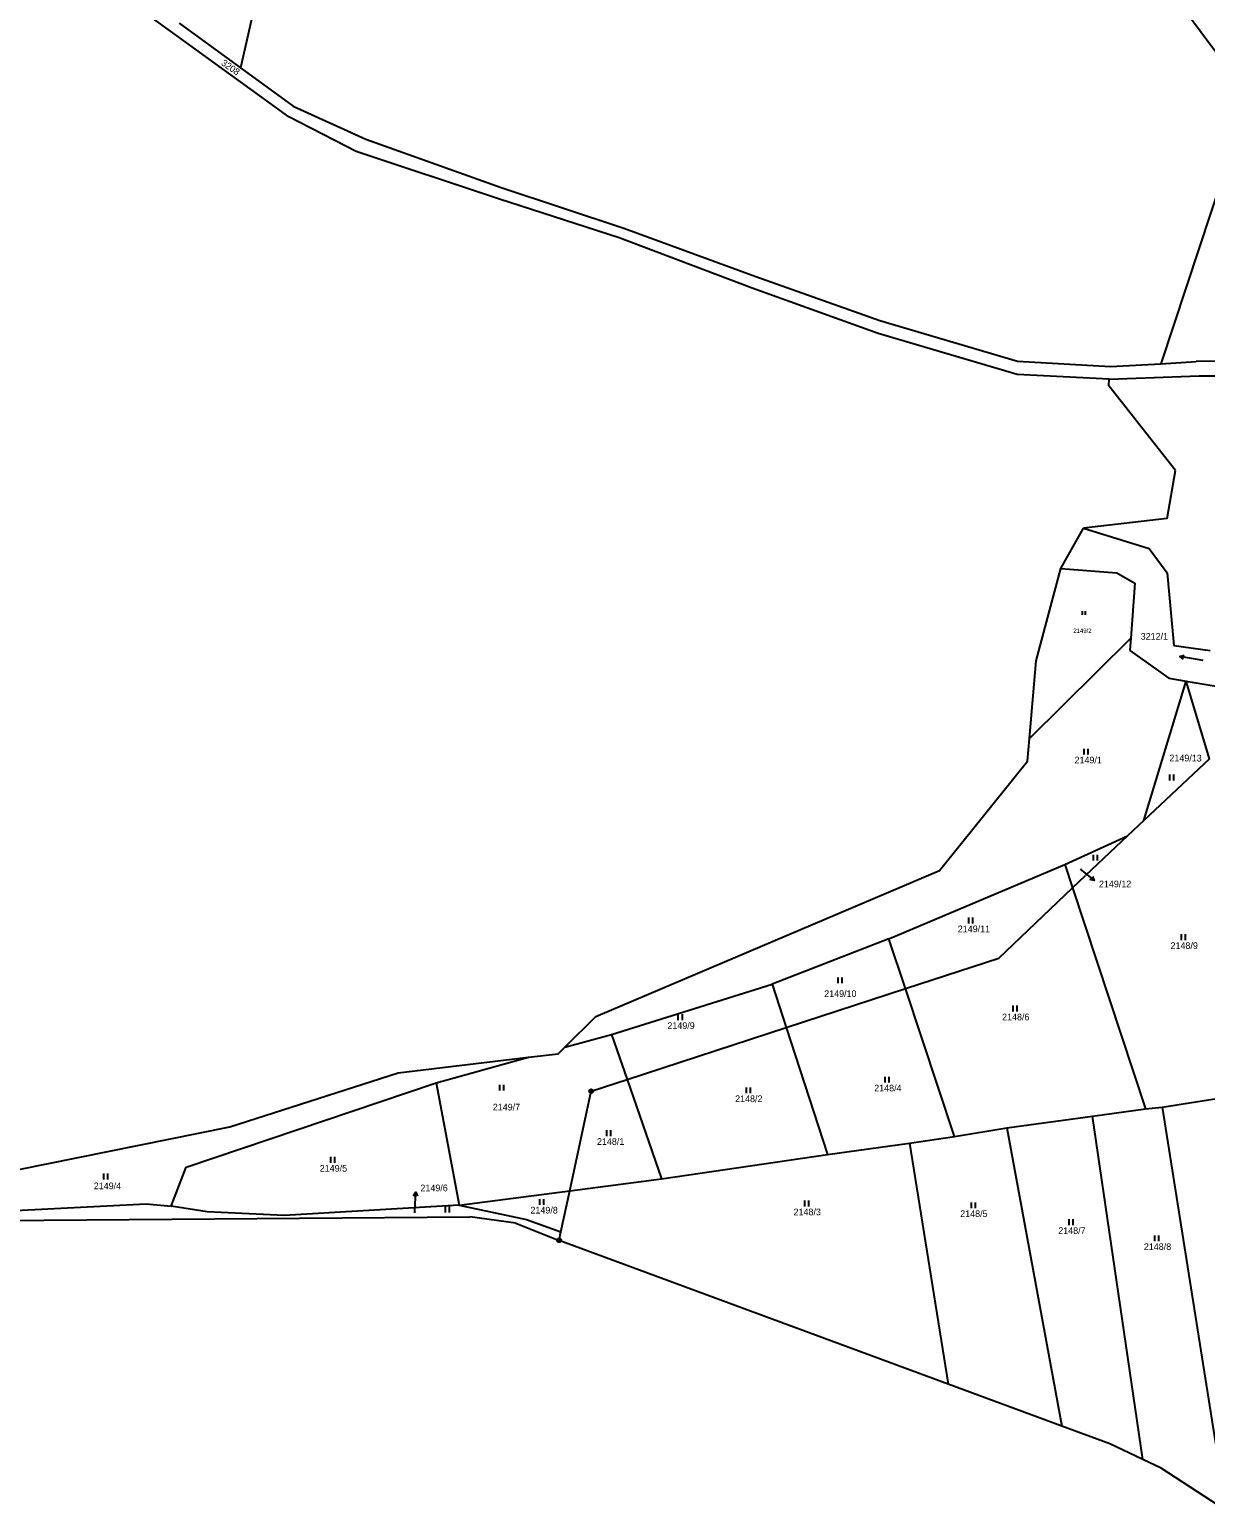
# Model space of a CAD drawing. Extents: x -736345 to -729997, y -1130177 to -1122501.
# Drawn here: x -732466.5 to -732167.4, y -1129158.7 to -1128781.9 of the extents above; entities that cross this region are included whole.
import ezdxf

# ---------------------------------------------------------------- set-up
doc = ezdxf.new("R2010")
doc.units = 0
for name, color, linetype in [('Vrstva 1', 7, 'Continuous'), ('Vrstva 13', 7, 'Continuous'), ('Vrstva 16', 7, 'Continuous'), ('Vrstva 18', 7, 'Continuous'), ('Vrstva 25', 7, 'Continuous')]:
    doc.layers.add(name, color=color, linetype=linetype)

msp = doc.modelspace()

# ---------------------------------------------------------------- linework, layer by layer
at = {"layer": 'Vrstva 1'}
for points in [[(-732403.79, -1128752.06), (-732412.82, -1128791.63)], [(-732184.86, -1128760.46), (-732156.26, -1128798.96)], [(-732429.09, -1128783.39), (-732455.66, -1128764.15)], [(-732428.4, -1128780.25), (-732412.82, -1128791.63)], [(-732400.49, -1128804.08), (-732429.09, -1128783.39)], [(-732412.82, -1128791.63), (-732399.38, -1128801.44)], [(-732156.26, -1128798.96), (-732178.67, -1128866.93)], [(-732383.4, -1128812.97), (-732400.49, -1128804.08)], [(-732399.38, -1128801.44), (-732380.93, -1128809.83)], [(-732380.93, -1128809.83), (-732346.49, -1128822.07)], [(-732347.2, -1128825.01), (-732383.4, -1128812.97)], [(-732346.49, -1128822.07), (-732315.31, -1128832.42)], [(-732316.45, -1128834.91), (-732347.2, -1128825.01)], [(-732282.67, -1128847.73), (-732316.45, -1128834.91)], [(-732315.31, -1128832.42), (-732281.69, -1128844.73)], [(-732281.69, -1128844.73), (-732250.2, -1128855.96)], [(-732250.59, -1128859.26), (-732282.67, -1128847.73)], [(-732250.2, -1128855.96), (-732215.16, -1128866.26)], [(-732215.21, -1128869.67), (-732250.59, -1128859.26)], [(-732215.16, -1128866.26), (-732191.49, -1128867.68)], [(-732191.49, -1128867.68), (-732178.67, -1128866.93)], [(-732178.67, -1128866.93), (-732169.67, -1128866.4)], [(-732133.66, -1128866.12), (-732169.67, -1128866.4)], [(-732191.84, -1128870.86), (-732215.21, -1128869.67)], [(-732191.95, -1128872.59), (-732191.84, -1128870.86)], [(-732174.99, -1128894.07), (-732191.95, -1128872.59)], [(-732191.84, -1128870.86), (-732168.96, -1128870.02)], [(-732168.96, -1128870.02), (-732133.37, -1128870.01)], [(-732177.12, -1128906.34), (-732174.99, -1128894.07)], [(-732177.12, -1128906.34), (-732198.39, -1128908.78)], [(-732204.13, -1128919.02), (-732198.39, -1128908.78)], [(-732198.39, -1128908.78), (-732181.69, -1128913.92)], [(-732181.69, -1128913.92), (-732177.09, -1128920.13)], [(-732210.4, -1128942.49), (-732204.13, -1128919.02)], [(-732204.13, -1128919.02), (-732189.88, -1128920.1)], [(-732189.88, -1128920.1), (-732185.33, -1128922.74)], [(-732177.09, -1128920.13), (-732175.38, -1128938.61)], [(-732185.33, -1128922.74), (-732186.34, -1128936.72)], [(-732212.14, -1128962.28), (-732186.34, -1128936.72)], [(-732186.34, -1128936.72), (-732186.57, -1128939.86)], [(-732186.57, -1128939.86), (-732176.67, -1128946.96)], [(-732175.38, -1128938.61), (-732166.12, -1128939.86)], [(-732212.14, -1128962.28), (-732210.4, -1128942.49)], [(-732182.99, -1128983.15), (-732172.28, -1128947.69)], [(-732176.67, -1128946.96), (-732172.28, -1128947.69)], [(-732172.28, -1128947.69), (-732149.35, -1128951.5)], [(-732166.29, -1128967.43), (-732172.28, -1128947.69)], [(-732212.64, -1128968.03), (-732212.14, -1128962.28)], [(-732234.98, -1128995.89), (-732212.64, -1128968.03)], [(-732166.29, -1128967.43), (-732182.99, -1128983.15)], [(-732182.99, -1128983.15), (-732187.16, -1128987.08)], [(-732203.12, -1128994.33), (-732187.16, -1128987.08)], [(-732187.16, -1128987.08), (-732197.89, -1128997.17)], [(-732322.43, -1129033.05), (-732234.98, -1128995.89)], [(-732247.85, -1129013.23), (-732203.12, -1128994.33)], [(-732203.12, -1128994.33), (-732201.15, -1129000.28)], [(-732201.15, -1129000.28), (-732197.89, -1128997.17)], [(-732219.92, -1129018.18), (-732201.15, -1129000.28)], [(-732201.15, -1129000.28), (-732182.56, -1129056.46)], [(-732247.85, -1129013.23), (-732277.58, -1129024.82)], [(-732243.64, -1129025.92), (-732247.85, -1129013.23)], [(-732243.64, -1129025.92), (-732219.92, -1129018.18)], [(-732318.45, -1129037.55), (-732277.58, -1129024.82)], [(-732277.58, -1129024.82), (-732274, -1129035.83)], [(-732274, -1129035.83), (-732243.64, -1129025.92)], [(-732231.16, -1129063.53), (-732243.64, -1129025.92)], [(-732330.32, -1129040.84), (-732322.43, -1129033.05)], [(-732330.32, -1129040.84), (-732318.45, -1129037.55)], [(-732318.45, -1129037.55), (-732314.48, -1129049.04)], [(-732314.48, -1129049.04), (-732274, -1129035.83)], [(-732274, -1129035.83), (-732263.47, -1129068.16)], [(-732339.56, -1129043.39), (-732332.01, -1129042.5)], [(-732332.01, -1129042.5), (-732330.32, -1129040.84)], [(-732372.67, -1129047.32), (-732339.56, -1129043.39)], [(-732363.08, -1129049.9), (-732339.56, -1129043.39)], [(-732426.61, -1129071.37), (-732363.08, -1129049.9)], [(-732415.55, -1129061.1), (-732372.67, -1129047.32)], [(-732363.08, -1129049.9), (-732357.21, -1129081.02)], [(-732323.6, -1129052.02), (-732314.48, -1129049.04)], [(-732314.48, -1129049.04), (-732305.73, -1129074.33)], [(-732329.06, -1129077.36), (-732323.6, -1129052.02)], [(-732178.32, -1129056.08), (-732161.2, -1129053.37)], [(-732196.08, -1129058.4), (-732182.56, -1129056.46)], [(-732182.56, -1129056.46), (-732178.32, -1129056.08)], [(-732178.32, -1129056.08), (-732162.1, -1129158.66)], [(-732477.27, -1129073.55), (-732415.55, -1129061.1)], [(-732231.16, -1129063.53), (-732217.9, -1129061.34)], [(-732217.9, -1129061.34), (-732196.08, -1129058.4)], [(-732217.9, -1129061.34), (-732203.92, -1129137.23)], [(-732183.25, -1129145.73), (-732196.08, -1129058.4)], [(-732242.62, -1129065.2), (-732231.16, -1129063.53)], [(-732305.73, -1129074.33), (-732263.47, -1129068.16)], [(-732263.47, -1129068.16), (-732242.62, -1129065.2)], [(-732242.62, -1129065.2), (-732232.81, -1129126.55)], [(-732430.47, -1129081.29), (-732426.61, -1129071.37)], [(-732329.06, -1129077.36), (-732305.73, -1129074.33)], [(-732357.21, -1129081.02), (-732329.06, -1129077.36)], [(-732331.31, -1129087.77), (-732329.06, -1129077.36)], [(-732485.24, -1129083.15), (-732436.78, -1129080.64)], [(-732436.78, -1129080.64), (-732430.47, -1129081.29)], [(-732421.26, -1129082.73), (-732430.47, -1129081.29)], [(-732401.7, -1129083.63), (-732421.26, -1129082.73)], [(-732357.21, -1129081.02), (-732401.7, -1129083.63)], [(-732357.21, -1129081.02), (-732340.08, -1129084.65)], [(-732340.08, -1129084.65), (-732331.31, -1129087.77)], [(-732331.78, -1129089.96), (-732331.31, -1129087.77)]]:
    msp.add_lwpolyline(points, dxfattribs=at)
at = {"layer": 'Vrstva 13'}
for points in [[(-732484.55, -1129084.96), (-732354.52, -1129083.95)], [(-732342.75, -1129085.62), (-732354.52, -1129083.95)], [(-732342.75, -1129085.62), (-732331.78, -1129089.96)], [(-732232.81, -1129126.55), (-732331.78, -1129089.96)], [(-732203.92, -1129137.23), (-732232.81, -1129126.55)], [(-732191.63, -1129141.77), (-732203.92, -1129137.23)], [(-732183.25, -1129145.73), (-732191.63, -1129141.77)], [(-732178.61, -1129147.93), (-732183.25, -1129145.73)], [(-732162.1, -1129158.66), (-732178.61, -1129147.93)]]:
    msp.add_lwpolyline(points, dxfattribs=at)
at = {"layer": 'Vrstva 16'}
for points in [[(-732199.2, -1128995.53), (-732197.96, -1128996.54)], [(-732368.48, -1129082.98), (-732368.38, -1129080.67)]]:
    msp.add_lwpolyline(points, dxfattribs=at)
at = {"layer": 'Vrstva 25'}
for points in [[(-732198.586, -1128930.852), (-732198.586, -1128929.847)], [(-732197.893, -1128930.852), (-732197.893, -1128929.847)], [(-732172.965, -1128942.073), (-732173.868, -1128941.415), (-732172.8, -1128941.087)], [(-732167.952, -1128942.405), (-732173.868, -1128941.415)], [(-732198.177, -1128966.385), (-732198.177, -1128964.885)], [(-732197.143, -1128966.385), (-732197.143, -1128964.885)], [(-732176.387, -1128972.945), (-732176.387, -1128971.445)], [(-732175.353, -1128972.945), (-732175.353, -1128971.445)], [(-732195.817, -1128993.355), (-732195.817, -1128991.855)], [(-732194.783, -1128993.355), (-732194.783, -1128991.855)], [(-732197.96, -1128996.54), (-732195.639, -1128998.44)], [(-732196.096, -1128997.419), (-732195.639, -1128998.44), (-732196.73, -1128998.193)], [(-732227.577, -1129009.335), (-732227.577, -1129007.835)], [(-732226.543, -1129009.335), (-732226.543, -1129007.835)], [(-732173.427, -1129013.595), (-732173.427, -1129012.095)], [(-732172.393, -1129013.595), (-732172.393, -1129012.095)], [(-732260.757, -1129024.555), (-732260.757, -1129023.055)], [(-732259.723, -1129024.555), (-732259.723, -1129023.055)], [(-732216.277, -1129031.745), (-732216.277, -1129030.245)], [(-732215.243, -1129031.745), (-732215.243, -1129030.245)], [(-732301.447, -1129033.955), (-732301.447, -1129032.455)], [(-732300.413, -1129033.955), (-732300.413, -1129032.455)], [(-732248.807, -1129049.825), (-732248.807, -1129048.325)], [(-732247.773, -1129049.825), (-732247.773, -1129048.325)], [(-732346.837, -1129051.875), (-732346.837, -1129050.375)], [(-732345.803, -1129051.875), (-732345.803, -1129050.375)], [(-732284.127, -1129052.555), (-732284.127, -1129051.055)], [(-732283.093, -1129052.555), (-732283.093, -1129051.055)], [(-732319.647, -1129063.435), (-732319.647, -1129061.935)], [(-732318.613, -1129063.435), (-732318.613, -1129061.935)], [(-732389.847, -1129070.245), (-732389.847, -1129068.745)], [(-732388.813, -1129070.245), (-732388.813, -1129068.745)], [(-732447.567, -1129074.455), (-732447.567, -1129072.955)], [(-732446.533, -1129074.455), (-732446.533, -1129072.955)], [(-732368.792, -1129078.651), (-732368.25, -1129077.673), (-732367.794, -1129078.694)], [(-732368.38, -1129080.67), (-732368.25, -1129077.673)], [(-732336.667, -1129080.945), (-732336.667, -1129079.445)], [(-732335.633, -1129080.945), (-732335.633, -1129079.445)], [(-732269.257, -1129081.345), (-732269.257, -1129079.845)], [(-732268.223, -1129081.345), (-732268.223, -1129079.845)], [(-732360.647, -1129082.835), (-732360.647, -1129081.335)], [(-732359.613, -1129082.835), (-732359.613, -1129081.335)], [(-732226.887, -1129081.795), (-732226.887, -1129080.295)], [(-732225.853, -1129081.795), (-732225.853, -1129080.295)], [(-732202.027, -1129086.105), (-732202.027, -1129084.605)], [(-732200.993, -1129086.105), (-732200.993, -1129084.605)], [(-732180.197, -1129090.185), (-732180.197, -1129088.685)], [(-732179.163, -1129090.185), (-732179.163, -1129088.685)]]:
    msp.add_lwpolyline(points, dxfattribs=at)
for centre, radius in [((-732323.6, -1129052.02), 0.5), ((-732323.6, -1129052.02), 0.032), ((-732331.78, -1129089.96), 0.5), ((-732331.78, -1129089.96), 0.032)]:
    msp.add_circle(centre, radius, dxfattribs=at)

# ---------------------------------------------------------------- texts
at = {"layer": 'Vrstva 16'}
for s, p in [('2149/12', (-732194.44, -1129000.14)), ('2149/6', (-732367.05, -1129077.47))]:
    msp.add_text(s, height=1.7, dxfattribs=at).set_placement(p)
at = {"layer": 'Vrstva 18'}
for s, rotation, p in [('3208', 325.20259, (-732417.902, -1128790.78)), ('2149/13', 359.50286, (-732176.519, -1128968.072))]:
    msp.add_text(s, height=1.7, rotation=rotation, dxfattribs=at).set_placement(p)
for s, height, p in [('2149/2', 1.1, (-732200.96, -1128935.41)), ('3212/1', 1.7, (-732183.82, -1128937.15)), ('2149/1', 1.7, (-732200.65, -1128968.62)), ('2149/12', 0.1, (-732199, -1128995.33)), ('2149/11', 1.7, (-732230.35, -1129011.57)), ('2148/9', 1.7, (-732176.23, -1129015.83)), ('2149/10', 1.7, (-732264.33, -1129028.04)), ('2149/9', 1.7, (-732304.22, -1129036.19)), ('2148/6', 1.7, (-732219.08, -1129033.98)), ('2148/2', 1.7, (-732286.99, -1129054.79)), ('2148/4', 1.7, (-732251.61, -1129052.06)), ('2149/7', 1.7, (-732348.64, -1129056.92)), ('2148/1', 1.7, (-732322.14, -1129065.67)), ('2149/5', 1.7, (-732392.66, -1129072.48)), ('2149/4', 1.7, (-732450.15, -1129076.95)), ('2149/6', 0.1, (-732368.28, -1129082.78)), ('2149/8', 1.7, (-732339.06, -1129083.13)), ('2148/3', 1.7, (-732272.13, -1129083.58)), ('2148/5', 1.7, (-732229.73, -1129084.03)), ('2148/7', 1.7, (-732204.79, -1129088.34)), ('2148/8', 1.7, (-732183.02, -1129092.42))]:
    msp.add_text(s, height=height, dxfattribs=at).set_placement(p)

doc.saveas('drawing.dxf')
